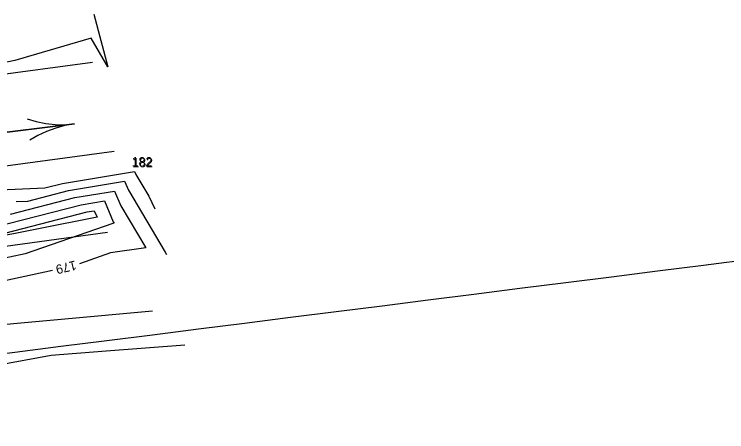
# Model space of a CAD drawing. Extents: x 2086416 to 2115205, y 575507 to 632762.
# Drawn here: x 2112802.6 to 2112956.5, y 581759 to 581849.1 of the extents above; entities that cross this region are included whole.
import ezdxf

# ---------------------------------------------------------------- set-up
doc = ezdxf.new("R2010")
doc.units = 0
for name, color, linetype in [('DTM Contours Major', 7, 'Continuous'), ('DTM Contours Minor', 7, 'Continuous'), ('DTM Contours Minor Text', 7, 'Continuous'), ('Exist Hydro Stream or Body of Water', 7, 'Continuous'), ('Exist Hydrographic FEMA Cross Section', 7, 'Continuous'), ('Exist Roads EOP', 7, 'Continuous'), ('Exist Roads EOP Text', 7, 'Continuous'), ('Exist Vegetation Woods Line', 7, 'Continuous')]:
    doc.layers.add(name, color=color, linetype=linetype)

msp = doc.modelspace()

# ---------------------------------------------------------------- linework, layer by layer
at = {"layer": 'DTM Contours Major'}
msp.add_lwpolyline([(2112803.04, 581808.65), (2112805.52, 581808.75), (2112814.35, 581811.03), (2112826.41, 581813.03), (2112827.25, 581811.07), (2112835.22, 581797.73), (2112835.47, 581797.2)], dxfattribs=at)
at = {"layer": 'DTM Contours Minor'}
for points in [[(2112819.78, 581849.06), (2112822.83, 581837.68), (2112819.19, 581843.91), (2112802.73, 581839.06), (2112796.49, 581837.76), (2112795.36, 581837.35), (2112787.17, 581834.46), (2112783.73, 581828.3), (2112781.2, 581822.95), (2112780.96, 581818.17), (2112783.45, 581815.96)], [(2112830.25, 581817.23), (2112830.34, 581817.21), (2112830.35, 581817.06), (2112830.25, 581817.23)], [(2112830.39, 581817.03), (2112830.41, 581817.01), (2112830.35, 581817.06), (2112830.39, 581817.03)], [(2112782.14, 581813.08), (2112778.5, 581811.75), (2112776.61, 581810.76), (2112783.13, 581811.18), (2112783.88, 581811.13), (2112799.56, 581811.18), (2112809.23, 581811.59), (2112813.01, 581812.56), (2112828.58, 581815.15), (2112828.87, 581814.46), (2112831.67, 581809.78), (2112832.94, 581807.1)], [(2112801.81, 581805.92), (2112815.69, 581809.49), (2112824.24, 581810.91), (2112825.62, 581807.68), (2112831.01, 581798.66), (2112823.41, 581797.54), (2112816.66, 581795.21)], [(2112667.8, 581788.21), (2112673.85, 581788.66), (2112682.18, 581789.27), (2112695.53, 581791.34), (2112699.44, 581791.98), (2112719.29, 581793.6), (2112731.39, 581795.57), (2112733.56, 581795.77), (2112738.64, 581797.56), (2112748.41, 581798.85), (2112759.68, 581800.3), (2112766.1, 581801.73), (2112775.78, 581802.35), (2112778.21, 581802.19), (2112791.8, 581802.81), (2112798.09, 581803.08), (2112817.03, 581807.95), (2112822.07, 581808.79), (2112824, 581804.29), (2112824.19, 581803.96), (2112823.92, 581803.92), (2112804.98, 581797.38), (2112794.7, 581795.17), (2112787.25, 581792.92)], [(2112702.58, 581788.79), (2112706.64, 581789.45), (2112715.19, 581790.15), (2112737.17, 581793.72), (2112738.12, 581793.81), (2112740.36, 581794.6), (2112744.66, 581795.16), (2112755.21, 581796.53), (2112762.91, 581797.78), (2112768.99, 581799.13), (2112773.33, 581799.4), (2112774.42, 581799.34), (2112794.13, 581800.23), (2112794.38, 581800.24), (2112818.37, 581806.41), (2112819.89, 581806.67), (2112820.5, 581805.25), (2112795.47, 581800.29), (2112794.66, 581800.01), (2112794.25, 581799.92), (2112777.01, 581794.73), (2112770.05, 581793.24), (2112747.45, 581789.73), (2112742.87, 581788.96)], [(2112810.84, 581793.78), (2112795.16, 581790.41), (2112790.93, 581789.14), (2112766.89, 581784.01), (2112762.05, 581783.26), (2112739.47, 581779.47), (2112734.79, 581778.75), (2112709.85, 581774.56), (2112707.71, 581774.23), (2112685.59, 581773.2), (2112680.84, 581771.94), (2112655.49, 581770.57), (2112653.07, 581770.03), (2112649.99, 581769.55), (2112633.68, 581767.05), (2112613.48, 581763.95)]]:
    msp.add_lwpolyline(points, dxfattribs=at)
at = {"layer": 'Exist Hydro Stream or Body of Water'}
msp.add_lwpolyline([(2112657.1, 581758.96), (2112680.78, 581759.84), (2112713.46, 581762.75), (2112743.23, 581764.08), (2112763.42, 581766.61), (2112786.45, 581770.23), (2112798.77, 581773.29), (2112810.55, 581775.49), (2112822.44, 581776.45), (2112839.49, 581777.68)], dxfattribs=at)
at = {"layer": 'Exist Hydrographic FEMA Cross Section'}
msp.add_lwpolyline([(2112961.42, 581796.09), (2112956.46, 581795.47), (2112951.5, 581794.84), (2112941.58, 581793.59), (2112931.67, 581792.34), (2112921.75, 581791.09), (2112911.83, 581789.84), (2112901.92, 581788.58), (2112892, 581787.33), (2112882.08, 581786.08), (2112872.17, 581784.83), (2112862.25, 581783.58), (2112852.33, 581782.33), (2112842.42, 581781.07), (2112832.5, 581779.82), (2112822.58, 581778.57), (2112812.67, 581777.32), (2112802.75, 581776.07), (2112792.83, 581774.82)], dxfattribs=at)
at = {"layer": 'Exist Roads EOP'}
for points in [[(2112647.29, 581814.65), (2112693.46, 581821.64), (2112739.24, 581827.62), (2112774.48, 581832.8), (2112796.9, 581835.72), (2112819.5, 581838.73)], [(2112824.17, 581819.47), (2112799.03, 581816.06), (2112765.01, 581811.56), (2112717.81, 581804.94), (2112683.85, 581800.4), (2112649.9, 581795.88)]]:
    msp.add_lwpolyline(points, dxfattribs=at)
at = {"layer": 'Exist Roads EOP Text'}
msp.add_line((2112805.66, 581824.19), (2112805.66, 581824.19), dxfattribs=at)
msp.add_lwpolyline([(2112805.39, 581826.46), (2112807.35, 581825.9), (2112809.39, 581825.5), (2112811.47, 581825.27), (2112813.54, 581825.21), (2112815.59, 581825.38), (2112795.73, 581822.99), (2112815.59, 581825.38), (2112813.56, 581825.06), (2112811.56, 581824.5), (2112809.6, 581823.79), (2112807.71, 581822.92), (2112805.93, 581821.92)], dxfattribs=at)
at = {"layer": 'Exist Vegetation Woods Line'}
for points in [[(2112650.08, 581779.87), (2112704.56, 581783.27), (2112778.59, 581795.96), (2112822.78, 581802.04)], [(2112832.5, 581784.96), (2112792.11, 581781.34), (2112731.05, 581770.16), (2112686.29, 581772.77), (2112655.35, 581770.76)]]:
    msp.add_lwpolyline(points, dxfattribs=at)

# ---------------------------------------------------------------- texts
at = {"layer": 'DTM Contours Minor Text'}
for p in [(2112827.97, 581816.23), (2112828.12, 581816.03)]:
    msp.add_text('182', height=2, dxfattribs=at).set_placement(p)
msp.add_text('179', height=2, rotation=193.7874, dxfattribs=at).set_placement((2112815.74, 581795.93))

doc.saveas('drawing.dxf')
